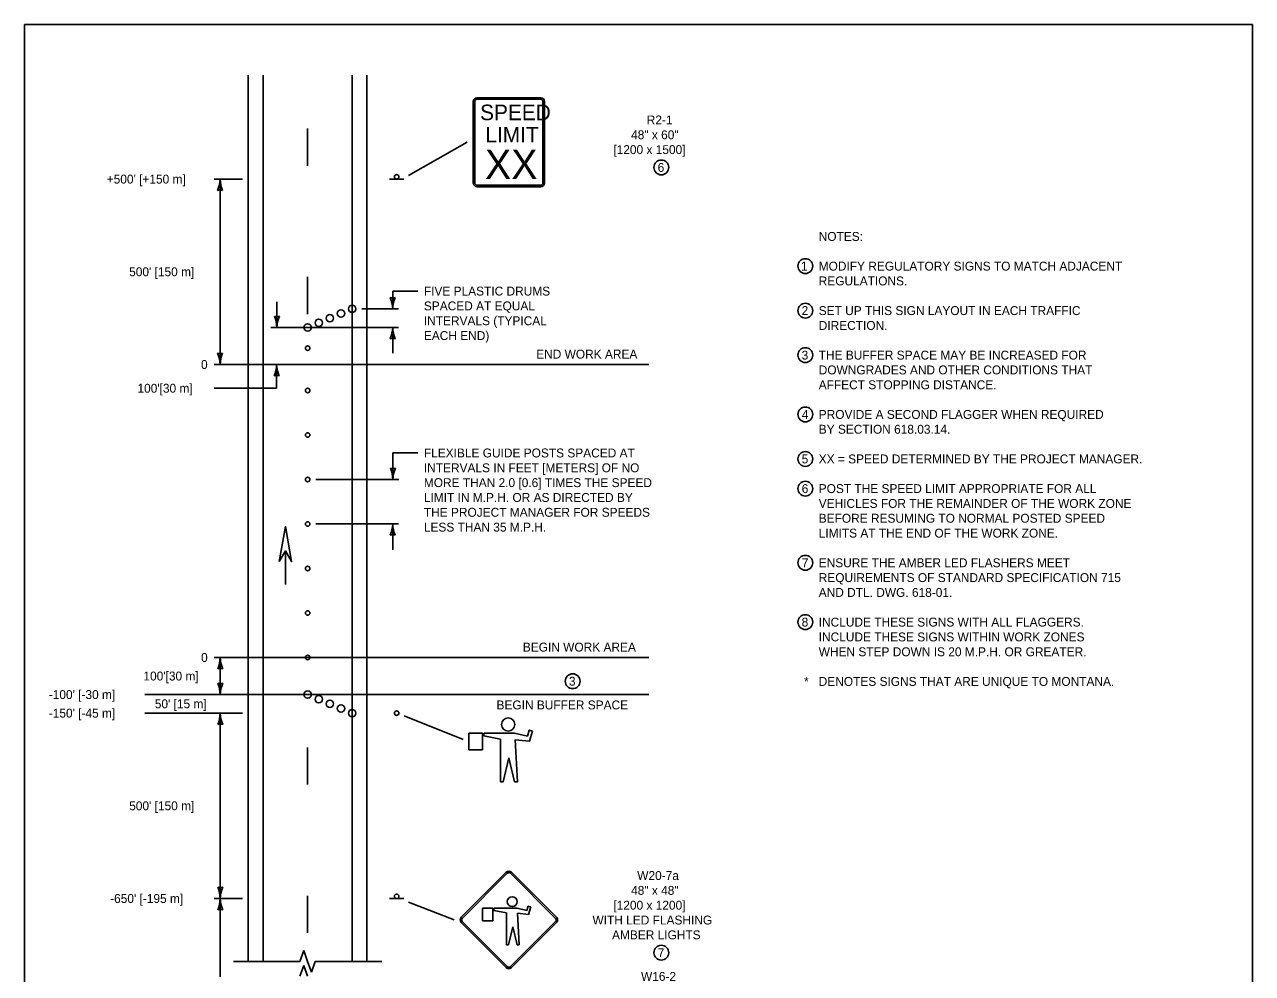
# Model space of a CAD drawing. Extents: x 49991.4 to 50021, y 49987.6 to 50011.4.
# Drawn here: x 50000.34 to 50008.61, y 50004.87 to 50011.26 of the extents above; entities that cross this region are included whole.
import ezdxf

# ---------------------------------------------------------------- set-up
doc = ezdxf.new("R2010")
doc.units = 0
for name, color, linetype in [('Level 1', 7, 'Continuous'), ('Level 2', 7, 'Continuous'), ('Level 3', 7, 'Continuous'), ('Level 6', 7, 'Continuous')]:
    doc.layers.add(name, color=color, linetype=linetype)

msp = doc.modelspace()

# ---------------------------------------------------------------- linework, layer by layer
at = {"layer": 'Level 1'}
for p, q in [((50001.8443, 50010.221), (50001.8443, 50010.921)), ((50001.9443, 50004.9471), (50001.9443, 50010.921)), ((50002.5443, 50004.9471), (50002.5443, 50010.921)), ((50002.6443, 50004.9471), (50002.6443, 50010.921)), ((50003.361, 50010.7446), (50003.361, 50010.1946)), ((50003.371, 50010.7446), (50003.371, 50010.1946)), ((50003.816, 50010.7696), (50003.386, 50010.7696)), ((50003.816, 50010.7596), (50003.386, 50010.7596)), ((50003.831, 50010.1946), (50003.831, 50010.7446)), ((50003.841, 50010.1946), (50003.841, 50010.7446)), ((50002.2443, 50010.3115), (50002.2443, 50010.5615)), ((50001.8443, 50004.9471), (50001.8443, 50010.221)), ((50002.8923, 50010.221), (50002.7963, 50010.221)), ((50003.386, 50010.1796), (50003.816, 50010.1796)), ((50003.386, 50010.1696), (50003.816, 50010.1696)), ((50002.2443, 50009.3115), (50002.2443, 50009.5615)), ((50002.0943, 50007.4888), (50002.0943, 50007.7147)), ((50002.0946, 50007.4888), (50002.0946, 50007.7147)), ((50003.3304, 50006.3736), (50003.3304, 50006.4861)), ((50003.3304, 50006.4861), (50003.4223, 50006.4861)), ((50003.4223, 50006.4861), (50003.4223, 50006.3736)), ((50003.6395, 50006.4854), (50003.4326, 50006.4854)), ((50003.4326, 50006.4854), (50003.4326, 50006.4668)), ((50003.7263, 50006.4654), (50003.6395, 50006.4854)), ((50003.739, 50006.505), (50003.7263, 50006.4654)), ((50003.761, 50006.4995), (50003.739, 50006.505)), ((50003.741, 50006.4307), (50003.761, 50006.4995)), ((50003.4326, 50006.4668), (50003.5451, 50006.4446)), ((50003.5451, 50006.4446), (50003.5451, 50006.1583)), ((50003.6582, 50006.1583), (50003.6434, 50006.4417)), ((50003.6434, 50006.4417), (50003.741, 50006.4307)), ((50002.2443, 50006.1388), (50002.2443, 50006.3888)), ((50003.4223, 50006.3736), (50003.3304, 50006.3736)), ((50003.5633, 50006.1583), (50003.6016, 50006.3196)), ((50003.6016, 50006.3196), (50003.6399, 50006.1583)), ((50003.5451, 50006.1583), (50003.5633, 50006.1583)), ((50003.6399, 50006.1583), (50003.6582, 50006.1583)), ((50003.5835, 50005.5484), (50003.2794, 50005.2444)), ((50003.5905, 50005.5414), (50003.2865, 50005.2373)), ((50003.9158, 50005.2373), (50003.6118, 50005.5414)), ((50003.9229, 50005.2444), (50003.6188, 50005.5484)), ((50002.2443, 50005.1388), (50002.2443, 50005.3888)), ((50002.8923, 50005.3709), (50002.7963, 50005.3709)), ((50003.4228, 50005.2207), (50003.4228, 50005.3057)), ((50003.4228, 50005.3057), (50003.4923, 50005.3057)), ((50003.4923, 50005.3057), (50003.4923, 50005.2207)), ((50003.6566, 50005.3053), (50003.5001, 50005.3053)), ((50003.5001, 50005.3053), (50003.5001, 50005.2912)), ((50003.5001, 50005.2912), (50003.5851, 50005.2744)), ((50003.5851, 50005.2744), (50003.5851, 50005.0579)), ((50003.7222, 50005.2901), (50003.6566, 50005.3053)), ((50003.6706, 50005.0579), (50003.6594, 50005.2722)), ((50003.6594, 50005.2722), (50003.7333, 50005.2639)), ((50003.7318, 50005.3201), (50003.7222, 50005.2901)), ((50003.7484, 50005.3159), (50003.7318, 50005.3201)), ((50003.7333, 50005.2639), (50003.7484, 50005.3159)), ((50003.2794, 50005.209), (50003.5835, 50004.905)), ((50003.2865, 50005.2161), (50003.5905, 50004.912)), ((50003.4923, 50005.2207), (50003.4228, 50005.2207)), ((50003.5989, 50005.0579), (50003.6278, 50005.1799)), ((50003.6118, 50004.912), (50003.9158, 50005.2161)), ((50003.6188, 50004.905), (50003.9229, 50005.209)), ((50003.6278, 50005.1799), (50003.6568, 50005.0579)), ((50003.5851, 50005.0579), (50003.5989, 50005.0579)), ((50003.6568, 50005.0579), (50003.6706, 50005.0579))]:
    msp.add_line(p, q, dxfattribs=at)
for points in [[(50008.6146, 50011.2628), (50000.3356, 50011.2628), (50000.3356, 50000.0624), (50008.6146, 50000.0624)], [(50002.0526, 50007.6424), (50002.0943, 50007.8789), (50002.1362, 50007.6424), (50002.0943, 50007.7146)]]:
    msp.add_lwpolyline(points, close=True, dxfattribs=at)
for points in [[(50003.7389, 50006.5048), (50003.7391, 50006.505)], [(50003.7404, 50006.4308), (50003.7413, 50006.4319)], [(50003.4219, 50006.3736), (50003.4223, 50006.374)], [(50003.7317, 50005.3199), (50003.7318, 50005.3201)], [(50003.7328, 50005.264), (50003.7335, 50005.2648)], [(50003.492, 50005.2207), (50003.4923, 50005.221)]]:
    msp.add_lwpolyline(points, dxfattribs=at)
for centre, radius in [((50002.8443, 50010.2362), 0.0152), ((50002.3942, 50009.2834), 0.025), ((50002.4692, 50009.3147), 0.025), ((50002.5442, 50009.3459), 0.025), ((50002.2442, 50009.2209), 0.025), ((50002.3192, 50009.2523), 0.025), ((50002.2444, 50009.0812), 0.015), ((50002.2443, 50008.7958), 0.015), ((50002.2443, 50008.4958), 0.015), ((50002.2443, 50008.1958), 0.015), ((50002.2443, 50007.8958), 0.015), ((50002.2443, 50007.5958), 0.015), ((50002.2443, 50007.2958), 0.015), ((50002.2443, 50006.9958), 0.015), ((50002.2442, 50006.7458), 0.025), ((50002.3192, 50006.7145), 0.025), ((50002.3942, 50006.6833), 0.025), ((50002.4692, 50006.652), 0.025), ((50002.5442, 50006.6208), 0.025), ((50002.8443, 50006.6209), 0.0152), ((50003.596, 50006.5443), 0.0442), ((50002.8443, 50005.3861), 0.0152), ((50003.6236, 50005.3498), 0.0334)]:
    msp.add_circle(centre, radius, dxfattribs=at)
for centre, radius, start, end in [((50003.386, 50010.7446), 0.025, 90, 180), ((50003.386, 50010.7446), 0.015, 90, 180), ((50003.816, 50010.7446), 0.025, 0, 90), ((50003.816, 50010.7446), 0.015, 0, 90), ((50003.386, 50010.1946), 0.025, 180, 270), ((50003.386, 50010.1946), 0.015, 180, 270), ((50003.816, 50010.1946), 0.025, 270, 0), ((50003.816, 50010.1946), 0.015, 270, 0), ((50003.6011, 50005.5308), 0.025, 45, 135), ((50003.6011, 50005.5308), 0.015, 45, 135), ((50003.2971, 50005.2268), 0.025, 135, 225), ((50003.9052, 50005.2268), 0.025, 315, 45.00024), ((50003.2971, 50005.2268), 0.015, 135, 225), ((50003.9052, 50005.2268), 0.015, 315, 45.00024), ((50003.6011, 50004.9227), 0.015, 225, 314.99957), ((50003.6011, 50004.9227), 0.025, 225, 314.99957)]:
    msp.add_arc(centre, radius, start, end, dxfattribs=at)
at = {"layer": 'Level 2'}
for centre in [(50004.6289, 50010.2996), (50005.6002, 50009.6344), (50005.6002, 50009.3344), (50005.6002, 50009.0344), (50005.6002, 50008.6344), (50005.6002, 50008.3344), (50005.6002, 50008.1344), (50005.6002, 50007.6344), (50005.6002, 50007.2344), (50004.0312, 50006.8359), (50004.629, 50005.0058)]:
    msp.add_circle(centre, 0.05, dxfattribs=at)
at = {"layer": 'Level 3'}
for p, q in [((50003.321, 50010.4696), (50002.9236, 50010.2459)), ((50001.6543, 50010.221), (50001.6143, 50010.221)), ((50001.6543, 50009.596), (50001.6543, 50010.221)), ((50001.6543, 50010.221), (50001.8043, 50010.221)), ((50001.6543, 50008.971), (50001.6543, 50009.596)), ((50002.9879, 50009.466), (50002.8178, 50009.466)), ((50002.8178, 50009.346), (50002.8178, 50009.466)), ((50002.0367, 50009.221), (50002.0367, 50009.3944)), ((50002.6092, 50009.346), (50002.8578, 50009.346)), ((50002.2041, 50009.221), (50001.9967, 50009.221)), ((50002.2041, 50009.221), (50002.8578, 50009.221)), ((50002.8178, 50009.0476), (50002.8178, 50009.221)), ((50001.6543, 50008.971), (50001.6143, 50008.971)), ((50001.6543, 50008.971), (50004.5445, 50008.971)), ((50002.0351, 50008.971), (50002.0351, 50008.811)), ((50002.0351, 50008.811), (50001.6143, 50008.811)), ((50002.8178, 50008.3745), (50002.9879, 50008.3745)), ((50002.8191, 50008.3745), (50002.8191, 50008.1958)), ((50002.2993, 50008.1958), (50002.8191, 50008.1958)), ((50002.8191, 50008.1958), (50002.8591, 50008.1958)), ((50002.2993, 50007.8958), (50002.8578, 50007.8958)), ((50002.8178, 50007.8958), (50002.8178, 50007.7224)), ((50001.6546, 50006.9958), (50001.6146, 50006.9958)), ((50001.6546, 50006.9958), (50003.0359, 50006.9958)), ((50001.6546, 50006.7459), (50001.6546, 50006.9958)), ((50003.0359, 50006.9958), (50004.5445, 50006.9958)), ((50002.8903, 50006.7459), (50001.1469, 50006.7459)), ((50002.8903, 50006.7459), (50004.5445, 50006.7459)), ((50001.1469, 50006.6209), (50001.8043, 50006.6209)), ((50001.6546, 50005.672), (50001.6546, 50006.6209)), ((50002.8954, 50006.6032), (50003.2929, 50006.4437)), ((50001.6546, 50005.3709), (50001.6546, 50005.672)), ((50001.6546, 50005.3709), (50001.6146, 50005.3709)), ((50001.6546, 50005.3709), (50001.8043, 50005.3709)), ((50001.6546, 50004.8434), (50001.6546, 50005.3709)), ((50002.9234, 50005.3457), (50003.2321, 50005.2268))]:
    msp.add_line(p, q, dxfattribs=at)
for centre, radius, start, end in [((50001.4322, 50010.2301), 0.2223, 337.45601, 357.63952), ((50001.887, 50010.2324), 0.233, 182.82731, 202.07716), ((50001.6543, 50010.0927), 0.0548, 72.13882, 107.86118), ((50002.8178, 50009.4742), 0.0548, 252.13882, 287.86118), ((50002.5851, 50009.3345), 0.233, 2.82731, 22.07716), ((50003.0399, 50009.3368), 0.2223, 157.45601, 177.63952), ((50002.0367, 50009.3493), 0.0548, 252.13882, 287.86118), ((50001.804, 50009.2095), 0.233, 2.82731, 22.07716), ((50002.2588, 50009.2119), 0.2223, 157.45601, 177.63952), ((50002.5957, 50009.2302), 0.2223, 337.45601, 357.63952), ((50003.0505, 50009.2325), 0.233, 182.82731, 202.07716), ((50002.8178, 50009.0928), 0.0548, 72.13882, 107.86118), ((50001.6543, 50009.0992), 0.0548, 252.13882, 287.86118), ((50001.4216, 50008.9595), 0.233, 2.82731, 22.07716), ((50001.8764, 50008.9618), 0.2223, 157.45601, 177.63952), ((50001.813, 50008.9801), 0.2223, 337.45601, 357.63952), ((50002.2678, 50008.9824), 0.233, 182.82731, 202.07716), ((50002.0351, 50008.8427), 0.0548, 72.13882, 107.86118), ((50002.8191, 50008.324), 0.0548, 252.13882, 287.86118), ((50002.5864, 50008.1843), 0.233, 2.82731, 22.07716), ((50003.0412, 50008.1866), 0.2223, 157.45601, 177.63952), ((50002.5957, 50007.9049), 0.2223, 337.45601, 357.63952), ((50003.0505, 50007.9072), 0.233, 182.82731, 202.07716), ((50002.8178, 50007.7675), 0.0548, 72.13882, 107.86118), ((50001.4324, 50007.005), 0.2223, 337.45601, 357.63952), ((50001.8873, 50007.0073), 0.233, 182.82731, 202.07716), ((50001.6546, 50006.8676), 0.0548, 72.13882, 107.86118), ((50001.6546, 50006.8741), 0.0548, 252.13882, 287.86118), ((50001.4219, 50006.7344), 0.233, 2.82731, 22.07716), ((50001.8767, 50006.7367), 0.2223, 157.45601, 177.63952), ((50001.4324, 50006.63), 0.2223, 337.45601, 357.63952), ((50001.8873, 50006.6323), 0.233, 182.82731, 202.07716), ((50001.6546, 50006.4926), 0.0548, 72.13882, 107.86118), ((50001.6546, 50005.4991), 0.0548, 252.13882, 287.86118), ((50001.4219, 50005.3594), 0.233, 2.82731, 22.07716), ((50001.8767, 50005.3617), 0.2223, 157.45601, 177.63952), ((50001.4324, 50005.38), 0.2223, 337.45601, 357.63952), ((50001.8873, 50005.3823), 0.233, 182.82731, 202.07716), ((50001.6546, 50005.2426), 0.0548, 72.13882, 107.86118)]:
    msp.add_arc(centre, radius, start, end, dxfattribs=at)
at = {"layer": 'Level 6'}
for p, q in [((50002.2184, 50005.0202), (50002.1925, 50004.9471)), ((50002.2184, 50005.0202), (50002.2443, 50004.9471)), ((50001.7443, 50004.9471), (50002.1925, 50004.9471)), ((50002.2184, 50004.9202), (50002.1925, 50004.8471)), ((50002.2184, 50004.9202), (50002.2443, 50004.8471)), ((50002.2443, 50004.9471), (50002.2702, 50004.874)), ((50002.2961, 50004.9471), (50002.2702, 50004.874)), ((50002.2961, 50004.9471), (50002.7443, 50004.9471))]:
    msp.add_line(p, q, dxfattribs=at)

# ---------------------------------------------------------------- texts
at = {"layer": 'Level 1'}
for s, height, p in [('SPEED', 0.10512, (50003.4072, 50010.618)), ('LIMIT', 0.10512, (50003.4427, 50010.4679)), ('XX', 0.19892, (50003.4396, 50010.2206))]:
    msp.add_text(s, height=height, dxfattribs=at).set_placement(p)
at = {"layer": 'Level 2'}
for s, p in [('R2-1', (50004.5307, 50010.5896)), ('48" x 60"', (50004.4252, 50010.4896)), ('[1200 x 1500]', (50004.3057, 50010.3896)), ('6', (50004.6044, 50010.2696)), ("+500' [+150 m]", (50000.8897, 50010.191)), ('NOTES:', (50005.6902, 50009.8044)), ('1', (50005.5705, 50009.6044)), ('MODIFY REGULATORY SIGNS TO MATCH ADJACENT', (50005.6902, 50009.6044)), ("500' [150 m]", (50001.0409, 50009.566)), ('REGULATIONS.', (50005.6902, 50009.5044)), ('FIVE PLASTIC DRUMS', (50003.0279, 50009.436)), ('SPACED AT EQUAL', (50003.0279, 50009.336)), ('2', (50005.575, 50009.3044)), ('SET UP THIS SIGN LAYOUT IN EACH TRAFFIC', (50005.6902, 50009.3044)), ('INTERVALS (TYPICAL', (50003.0279, 50009.236)), ('DIRECTION.', (50005.6902, 50009.2044)), ('EACH END)', (50003.0279, 50009.136)), ('END WORK AREA', (50003.7853, 50009.011)), ('3', (50005.575, 50009.0044)), ('THE BUFFER SPACE MAY BE INCREASED FOR', (50005.6902, 50009.0044)), ('0', (50001.5255, 50008.941)), ('DOWNGRADES AND OTHER CONDITIONS THAT', (50005.6902, 50008.9044)), ("100'[30 m]", (50001.0969, 50008.781)), ('AFFECT STOPPING DISTANCE.', (50005.6902, 50008.8044)), ('4', (50005.5762, 50008.6044)), ('PROVIDE A SECOND FLAGGER WHEN REQUIRED', (50005.6902, 50008.6044)), ('BY SECTION 618.03.14.', (50005.6902, 50008.5044)), ('FLEXIBLE GUIDE POSTS SPACED AT  ', (50003.0279, 50008.3446)), ('INTERVALS IN FEET [METERS] OF NO ', (50003.0279, 50008.2446)), ('5', (50005.5753, 50008.3044)), ('XX = SPEED DETERMINED BY THE PROJECT MANAGER.', (50005.6902, 50008.3044)), ('MORE THAN 2.0 [0.6] TIMES THE SPEED ', (50003.0279, 50008.1446)), ('6', (50005.5757, 50008.1044)), ('POST THE SPEED LIMIT APPROPRIATE FOR ALL ', (50005.6902, 50008.1044)), ('LIMIT IN M.P.H. OR AS DIRECTED BY ', (50003.0279, 50008.0446)), ('VEHICLES FOR THE REMAINDER OF THE WORK ZONE', (50005.6902, 50008.0044)), ('THE PROJECT MANAGER FOR SPEEDS ', (50003.0279, 50007.9446)), ('LESS THAN 35 M.P.H.', (50003.0279, 50007.8446)), ('BEFORE RESUMING TO NORMAL POSTED SPEED', (50005.6902, 50007.9044)), ('LIMITS AT THE END OF THE WORK ZONE.', (50005.6902, 50007.8044)), ('7', (50005.5764, 50007.6044)), ('ENSURE THE AMBER LED FLASHERS MEET ', (50005.6902, 50007.6044)), ('REQUIREMENTS OF STANDARD SPECIFICATION 715', (50005.6902, 50007.5044)), ('AND DTL. DWG. 618-01.', (50005.6902, 50007.4044)), ('8', (50005.5752, 50007.2044)), ('INCLUDE THESE SIGNS WITH ALL FLAGGERS. ', (50005.6902, 50007.2044)), ('INCLUDE THESE SIGNS WITHIN WORK ZONES', (50005.6902, 50007.1044)), ('BEGIN WORK AREA', (50003.6953, 50007.0358)), ('WHEN STEP DOWN IS 20 M.P.H. OR GREATER.', (50005.6902, 50007.0044)), ('0', (50001.5258, 50006.9658)), ("100'[30 m]", (50001.1372, 50006.8408)), ('3', (50004.006, 50006.8059)), ('*', (50005.5916, 50006.8044)), ('DENOTES SIGNS THAT ARE UNIQUE TO MONTANA.', (50005.6902, 50006.8044)), ("-100' [-30 m]", (50000.4989, 50006.7159)), ("-150' [-45 m]", (50000.4989, 50006.5909)), ("50' [15 m]", (50001.2137, 50006.6535)), ('BEGIN BUFFER SPACE', (50003.5178, 50006.6459)), ("500' [150 m]", (50001.0412, 50005.9659)), ('W20-7a', (50004.4666, 50005.4958)), ('48" x 48"', (50004.4252, 50005.3958)), ("-650' [-195 m]", (50000.9127, 50005.3409)), ('[1200 x 1200]', (50004.3057, 50005.2958)), (' WITH LED FLASHING', (50004.1425, 50005.1958)), ('AMBER LIGHTS', (50004.2967, 50005.0958)), ('7', (50004.6052, 50004.9758)), ('W16-2', (50004.492, 50004.8158))]:
    msp.add_text(s, height=0.06, dxfattribs=at).set_placement(p)

doc.saveas('drawing.dxf')
